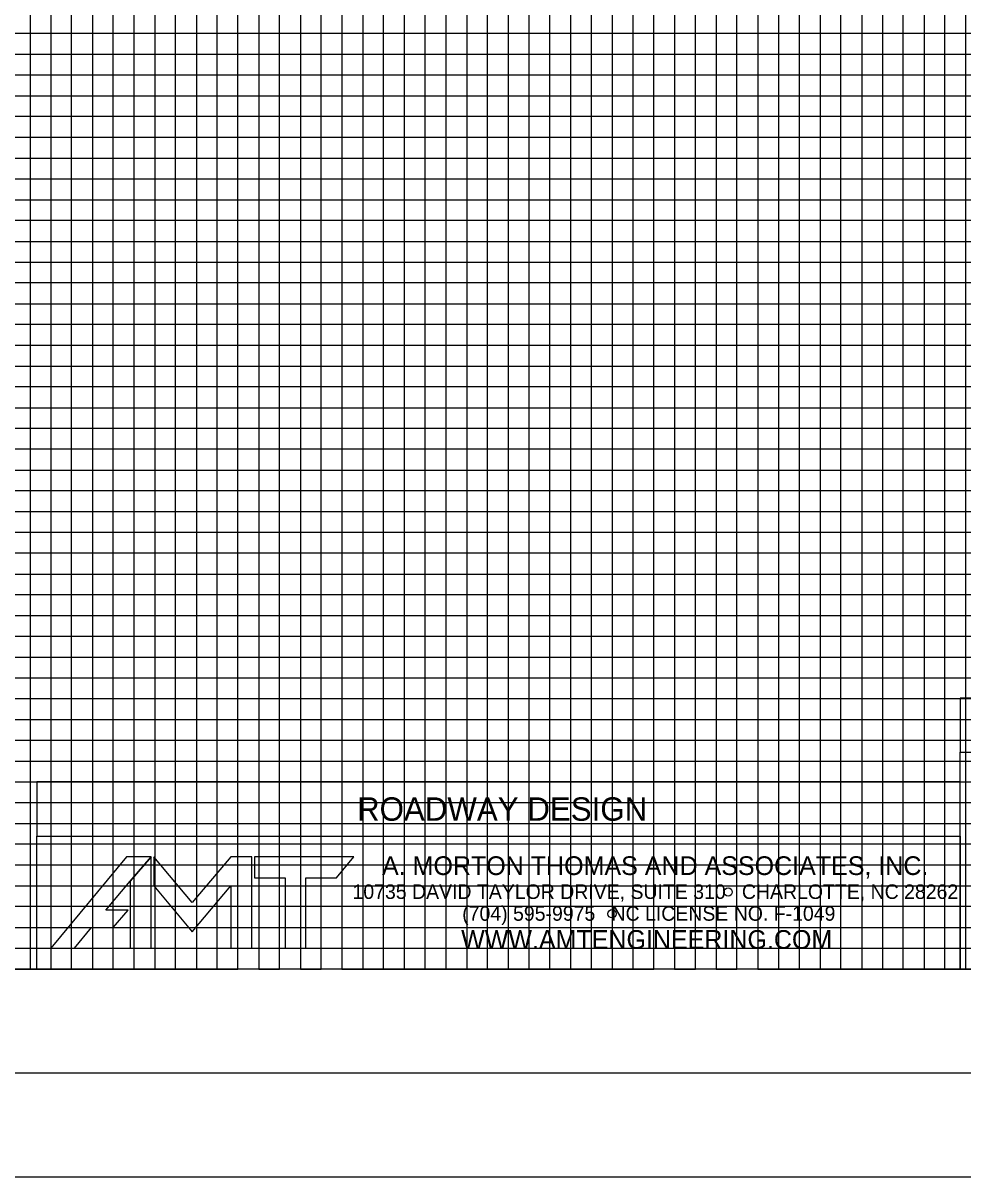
# Model space of a CAD drawing. Extents: x 1524869 to 1526553, y 501099 to 502199.
# Drawn here: x 1526209.4 to 1526435.4, y 501098.6 to 501376.1 of the extents above; entities that cross this region are included whole.
import ezdxf

# ---------------------------------------------------------------- set-up
doc = ezdxf.new("R2010")
doc.units = 0
for name, color, linetype in [('Prop Grid Mask', 7, 'Continuous'), ('Prop Horizontal Alignment Curve and Spiral Data', 7, 'Continuous'), ('Sheet Block Title CELL', 7, 'Continuous'), ('Sheet Layout Profile Border Port 2', 7, 'Continuous'), ('Sheet Plot Border Outside CELL', 7, 'Continuous'), ('Sheet Profile CELL', 7, 'Continuous'), ('Sheet Profile Grid Major CELL', 7, 'Continuous'), ('Sheet Profile Grid Middle CELL', 7, 'Continuous'), ('Sheet Profile Grid Minor CELL', 7, 'Continuous')]:
    doc.layers.add(name, color=color, linetype=linetype)

msp = doc.modelspace()

# ---------------------------------------------------------------- linework, layer by layer
at = {"layer": 'Prop Grid Mask'}
for points in [[(1526434.75, 501200.68), (1526536.08, 501200.68), (1526536.08, 501213.73), (1526434.75, 501213.73)], [(1526434.75, 501200.68), (1526536.08, 501200.68), (1526536.08, 501148.56), (1526434.75, 501148.56)], [(1526212.71, 501180.52), (1526434.75, 501180.52), (1526434.75, 501193.56), (1526212.71, 501193.56)], [(1526212.71, 501180.52), (1526434.75, 501180.52), (1526434.75, 501148.56), (1526212.71, 501148.56)]]:
    msp.add_lwpolyline(points, close=True, dxfattribs=at)
at = {"layer": 'Sheet Block Title CELL'}
msp.add_lwpolyline([(1526212.71, 501180.52), (1526434.75, 501180.52), (1526434.75, 501148.56), (1526212.71, 501148.56)], close=True, dxfattribs=at)
for points in [[(1526235.14, 501169.66), (1526240.17, 501175.56), (1526234.29, 501175.56), (1526216.06, 501153.6), (1526221.76, 501153.6), (1526225.85, 501158.54), (1526231.07, 501158.54), (1526234.65, 501162.69), (1526229.26, 501162.69), (1526235.14, 501169.66)], [(1526240.17, 501153.6), (1526240.17, 501175.56), (1526235.14, 501169.66), (1526235.14, 501153.6), (1526240.17, 501153.6)], [(1526250.04, 501157.47), (1526259.37, 501168.59), (1526259.37, 501153.6), (1526264.4, 501153.6), (1526264.4, 501175.56), (1526259.37, 501175.56), (1526250.04, 501164.6), (1526240.82, 501175.56), (1526240.82, 501168.57), (1526250.04, 501157.47)], [(1526277.43, 501153.6), (1526277.43, 501170.52), (1526284.73, 501170.52), (1526288.93, 501175.56), (1526265.05, 501175.56), (1526265.05, 501170.52), (1526272.4, 501170.52), (1526272.4, 501153.6), (1526277.43, 501153.6)]]:
    msp.add_lwpolyline(points, dxfattribs=at)
for centre in [(1526378.94, 501167.08), (1526351.02, 501161.86)]:
    msp.add_circle(centre, 1, dxfattribs=at)
at = {"layer": 'Sheet Layout Profile Border Port 2'}
msp.add_lwpolyline([(1525086.08, 501648.56), (1526486.08, 501648.56), (1526486.08, 501148.56), (1525086.08, 501148.56)], close=True, dxfattribs=at)
at = {"layer": 'Sheet Plot Border Outside CELL'}
msp.add_lwpolyline([(1524869.08, 501098.56), (1526553.08, 501098.56), (1526553.08, 502198.56), (1524869.08, 502198.56)], close=True, dxfattribs=at)
at = {"layer": 'Sheet Profile CELL'}
for p, q in [((1526536.08, 501148.56), (1525036.08, 501148.56)), ((1525036.08, 501123.56), (1526536.08, 501123.56))]:
    msp.add_line(p, q, dxfattribs=at)
msp.add_lwpolyline([(1526536.08, 502173.56), (1525036.08, 502173.56), (1525036.08, 501123.56), (1526536.08, 501123.56)], close=True, dxfattribs=at)
at = {"layer": 'Sheet Profile Grid Major CELL'}
for points in [[(1525986.08, 501148.56), (1526036.08, 501148.56), (1526036.08, 501648.56), (1526086.08, 501648.56), (1526086.08, 501148.56), (1526136.08, 501148.56), (1526136.08, 501648.56), (1526186.08, 501648.56), (1526186.08, 501148.56), (1526236.08, 501148.56), (1526236.08, 501648.56), (1526286.08, 501648.56), (1526286.08, 501148.56), (1526336.08, 501148.56), (1526336.08, 501648.56), (1526386.08, 501648.56), (1526386.08, 501148.56), (1526436.08, 501148.56), (1526436.08, 501148.56), (1526436.08, 501648.56), (1526486.08, 501648.56), (1526486.08, 501148.56)], [(1526536.08, 501348.56), (1525036.08, 501348.56), (1525036.08, 501298.56), (1526536.08, 501298.56)], [(1526536.08, 501248.56), (1525036.08, 501248.56), (1525036.08, 501248.56), (1525036.08, 501198.56), (1526536.08, 501198.56)], [(1526536.08, 501148.56), (1525036.08, 501148.56)]]:
    msp.add_lwpolyline(points, dxfattribs=at)
at = {"layer": 'Sheet Profile Grid Middle CELL'}
for points in [[(1526011.08, 501148.56), (1526061.08, 501148.56), (1526061.08, 501648.56), (1526111.08, 501648.56), (1526111.08, 501148.56), (1526161.08, 501148.56), (1526161.08, 501648.56), (1526211.08, 501648.56), (1526211.08, 501148.56), (1526261.08, 501148.56), (1526261.08, 501648.56), (1526311.08, 501648.56), (1526311.08, 501148.56), (1526361.08, 501148.56), (1526361.08, 501648.56), (1526411.08, 501648.56), (1526411.08, 501148.56), (1526461.08, 501148.56), (1526461.08, 501648.56)], [(1526536.08, 501373.56), (1525036.08, 501373.56), (1525036.08, 501323.56), (1526536.08, 501323.56)], [(1526536.08, 501273.56), (1525036.08, 501273.56), (1525036.08, 501223.56), (1526536.08, 501223.56)], [(1526536.08, 501173.56), (1525036.08, 501173.56)]]:
    msp.add_lwpolyline(points, dxfattribs=at)
at = {"layer": 'Sheet Profile Grid Minor CELL'}
for p, q in [((1525086.08, 501368.56), (1526486.08, 501368.56)), ((1526486.08, 501363.56), (1525086.08, 501363.56)), ((1525086.08, 501358.56), (1526486.08, 501358.56)), ((1526486.08, 501353.56), (1525086.08, 501353.56)), ((1525086.08, 501343.56), (1526486.08, 501343.56)), ((1526486.08, 501338.56), (1525086.08, 501338.56)), ((1525086.08, 501333.56), (1526486.08, 501333.56)), ((1526486.08, 501328.56), (1525086.08, 501328.56)), ((1525086.08, 501318.56), (1526486.08, 501318.56)), ((1526486.08, 501313.56), (1525086.08, 501313.56)), ((1525086.08, 501308.56), (1526486.08, 501308.56)), ((1526486.08, 501303.56), (1525086.08, 501303.56)), ((1525086.08, 501293.56), (1526486.08, 501293.56)), ((1526486.08, 501288.56), (1525086.08, 501288.56)), ((1525086.08, 501283.56), (1526486.08, 501283.56)), ((1526486.08, 501278.56), (1525086.08, 501278.56)), ((1525086.08, 501268.56), (1526486.08, 501268.56)), ((1526486.08, 501263.56), (1525086.08, 501263.56)), ((1525086.08, 501258.56), (1526486.08, 501258.56)), ((1526486.08, 501253.56), (1525086.08, 501253.56)), ((1525086.08, 501243.56), (1526486.08, 501243.56)), ((1526486.08, 501238.56), (1525086.08, 501238.56)), ((1525086.08, 501233.56), (1526486.08, 501233.56)), ((1526486.08, 501228.56), (1525086.08, 501228.56)), ((1525086.08, 501218.56), (1526486.08, 501218.56)), ((1526486.08, 501213.56), (1525086.08, 501213.56)), ((1525086.08, 501208.56), (1526486.08, 501208.56)), ((1526486.08, 501203.56), (1525086.08, 501203.56)), ((1525086.08, 501193.56), (1526486.08, 501193.56)), ((1526486.08, 501188.56), (1525086.08, 501188.56)), ((1525086.08, 501183.56), (1526486.08, 501183.56)), ((1526486.08, 501178.56), (1525086.08, 501178.56)), ((1525086.08, 501168.56), (1526486.08, 501168.56)), ((1526486.08, 501163.56), (1525086.08, 501163.56)), ((1525086.08, 501158.56), (1526486.08, 501158.56)), ((1525086.08, 501153.56), (1526486.08, 501153.56))]:
    msp.add_line(p, q, dxfattribs=at)
for points in [[(1526216.08, 501648.56), (1526216.08, 501148.56), (1526221.08, 501148.56), (1526221.08, 501648.56)], [(1526226.08, 501648.56), (1526226.08, 501148.56)], [(1526226.08, 501148.56), (1526231.08, 501148.56), (1526231.08, 501648.56)], [(1526241.08, 501648.56), (1526241.08, 501148.56), (1526246.08, 501148.56), (1526246.08, 501648.56)], [(1526251.08, 501648.56), (1526251.08, 501148.56), (1526256.08, 501148.56), (1526256.08, 501648.56)], [(1526266.08, 501648.56), (1526266.08, 501148.56), (1526271.08, 501148.56), (1526271.08, 501648.56)], [(1526276.08, 501648.56), (1526276.08, 501148.56), (1526281.08, 501148.56), (1526281.08, 501648.56)], [(1526291.08, 501648.56), (1526291.08, 501148.56), (1526296.08, 501148.56), (1526296.08, 501648.56)], [(1526301.08, 501648.56), (1526301.08, 501148.56), (1526306.08, 501148.56), (1526306.08, 501648.56)], [(1526316.08, 501648.56), (1526316.08, 501148.56), (1526321.08, 501148.56), (1526321.08, 501648.56)], [(1526326.08, 501648.56), (1526326.08, 501148.56), (1526331.08, 501148.56), (1526331.08, 501648.56)], [(1526341.08, 501648.56), (1526341.08, 501148.56), (1526346.08, 501148.56), (1526346.08, 501648.56)], [(1526351.08, 501648.56), (1526351.08, 501148.56), (1526356.08, 501148.56), (1526356.08, 501648.56)], [(1526366.08, 501648.56), (1526366.08, 501148.56), (1526371.08, 501148.56), (1526371.08, 501648.56)], [(1526376.08, 501648.56), (1526376.08, 501148.56), (1526381.08, 501148.56), (1526381.08, 501648.56)], [(1526391.08, 501648.56), (1526391.08, 501148.56), (1526396.08, 501148.56), (1526396.08, 501648.56)], [(1526401.08, 501648.56), (1526401.08, 501148.56), (1526406.08, 501148.56), (1526406.08, 501648.56)], [(1526416.08, 501648.56), (1526416.08, 501148.56), (1526421.08, 501148.56), (1526421.08, 501648.56)], [(1526426.08, 501648.56), (1526426.08, 501148.56), (1526431.08, 501148.56), (1526431.08, 501648.56)]]:
    msp.add_lwpolyline(points, dxfattribs=at)

# ---------------------------------------------------------------- texts
at = {"layer": 'Prop Horizontal Alignment Curve and Spiral Data'}
msp.add_text('ROADWAY DESIGN', height=5.625, rotation=360, dxfattribs=at).set_placement((1526289.7, 501184.23))
at = {"layer": 'Sheet Block Title CELL'}
for s, height, p in [('A. MORTON THOMAS AND ASSOCIATES, INC.', 4.5, (1526295.72, 501171.17)), ('10735 DAVID TAYLOR DRIVE, SUITE 310   CHARLOTTE, NC 28262', 3.5, (1526288.62, 501165.42)), ('(704) 595-9975   NC LICENSE NO. F-1049', 3.5, (1526315, 501160.17)), ('WWW.AMTENGINEERING.COM', 4.5, (1526314.74, 501153.42))]:
    msp.add_text(s, height=height, rotation=359.9995, dxfattribs=at).set_placement(p)

doc.saveas('drawing.dxf')
